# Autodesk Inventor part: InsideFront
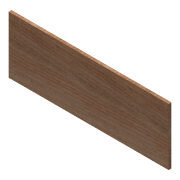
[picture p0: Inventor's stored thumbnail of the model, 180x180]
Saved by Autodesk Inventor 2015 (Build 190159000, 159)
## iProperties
Created: 2016-02
Part Number: InsideFront
Material: Wood (Birch)
Document SubType Name: Modeling
Designer: Hafliði
Density: 0.55 g/cm^3
Appearance: Birch - Natural Polished
Mass: 616 g
Surface Area: 2392 cm^2
Volume: 1120 cm^3
Author: Hafliði
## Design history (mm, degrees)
sketch "Sketch1"
  geometry: L1 (-280, 100)-(280, 100); L2 (280, 100)-(280, -100); L3 (280, -100)-(-280, -100); L4 (-280, -100)-(-280, 100); L5 (-280, 100)-(280, -100); L6 (280, 100)-(-280, -100); 1 further point
  constraints: 12 end point, 2 midpoint, 2 parallel, 1 horizontal, 1 perpendicular
  dimensions: "d0" = 560 distance of L2.end L3.end; "d1" = 200 distance of L1.end L2.end
extrude "Extrusion1" new body sketch "Sketch1" distance "d2" = 10; taper "d3" = 0 deg
body "Solid1"
